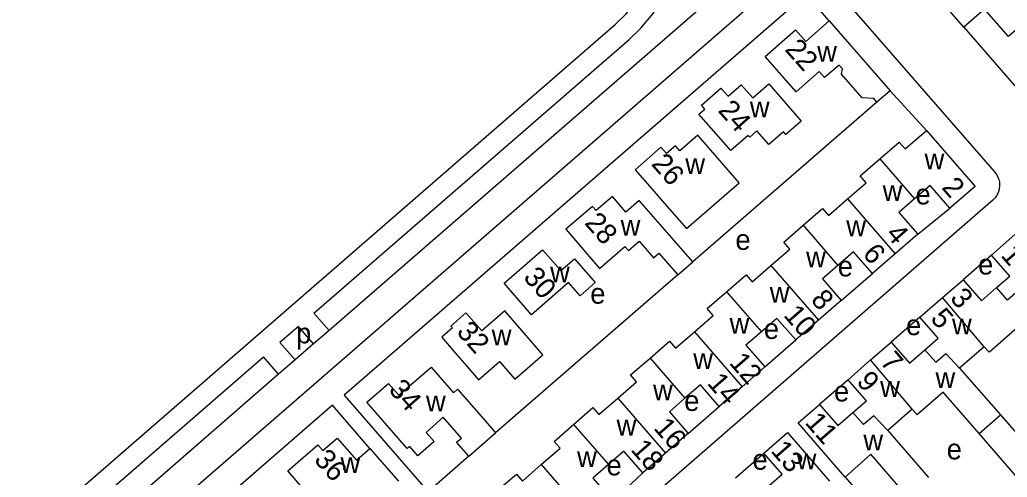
# Model space of a CAD drawing. Extents: x 155854 to 157362, y 383621 to 384685.
# Drawn here: x 155992.5 to 156185.4, y 384135.3 to 384224.7 of the extents above; entities that cross this region are included whole.
import ezdxf

# ---------------------------------------------------------------- set-up
doc = ezdxf.new("R2010")
doc.units = 0
for name, color, linetype in [('BLT_Basislijn', 7, 'Continuous'), ('BLT_Bebouwing', 7, 'Continuous'), ('BLT_Centroide', 7, 'Continuous'), ('BLT_Huisnummer', 7, 'Continuous'), ('BLT_Huisnummer_ tussenligend', 7, 'Continuous'), ('BLT_Onderverdeling_panden', 7, 'Continuous')]:
    doc.layers.add(name, color=color, linetype=linetype)

msp = doc.modelspace()

# ---------------------------------------------------------------- linework, layer by layer
at = {"layer": 'BLT_Basislijn'}
for p, q in [((156176.89, 384223.23), (156162.2, 384240.16)), ((156139.33, 384239), (156052.94, 384163.95)), ((156026.31, 384132.88), (156143.26, 384234.47)), ((156148.96, 384234.01), (156182.91, 384194.98)), ((156042.02, 384165.73), (156108.92, 384223.85)), ((156169.63, 384203.05), (156162.51, 384210.8)), ((156159.95, 384208.58), (156123.96, 384177.36)), ((156182.59, 384189.41), (156111.16, 384127.33)), ((156167.93, 384182.79), (156174.2, 384187.84)), ((156182.31, 384178.69), (156176.77, 384173.87)), ((156121.06, 384174.84), (156085.47, 384143.92)), ((156152.99, 384169.8), (156159.06, 384175.08)), ((156052.94, 384163.95), (156049.99, 384167.35)), ((156168.33, 384166.54), (156162.73, 384161.67)), ((155892.15, 384035.54), (156042.02, 384165.73)), ((156046.95, 384164.71), (156043.35, 384161.59)), ((156049.9, 384161.31), (156046.95, 384164.71)), ((156052.94, 384163.95), (156049.9, 384161.31)), ((156046.3, 384158.19), (156043.35, 384161.59)), ((156049.9, 384161.31), (156046.3, 384158.19)), ((156138.04, 384156.82), (156144.11, 384162.09)), ((156043.1, 384155.4), (156040.15, 384158.81)), ((156046.3, 384158.19), (156043.1, 384155.4)), ((156043.1, 384155.4), (155952.77, 384076.94)), ((156154.3, 384154.32), (156148.71, 384149.46)), ((156060.94, 384140.9), (156053.63, 384149.33)), ((156123.09, 384143.83), (156129.16, 384149.1)), ((156080.23, 384139.36), (156072.3, 384132.42)), ((156132.32, 384135.17), (156137.86, 384139.98)), ((156108.36, 384130.6), (156114.21, 384136.12)), ((156153.72, 384135.29), (156168.72, 384118.08))]:
    msp.add_line(p, q, dxfattribs=at)
for points in [[(156108.92, 384223.85), (156110.92, 384225.77), (156112.94, 384228.19), (156114.66, 384231.15), (156116.16, 384234.58)], [(156111.55, 384220.83), (156113.84, 384223.04), (156116.23, 384225.88), (156118.23, 384229.34), (156119.94, 384233.27)], [(156150.65, 384224.45), (156146.11, 384229.67), (156055.9, 384151.3), (156072.3, 384132.42)], [(156049.99, 384167.35), (156111.55, 384220.83)], [(156182.91, 384194.98), (156183.37, 384194.36), (156183.58, 384193.92), (156183.74, 384193.43), (156183.87, 384192.91), (156183.89, 384192.26), (156183.82, 384191.55), (156183.61, 384190.88), (156183.3, 384190.28), (156183.06, 384189.86), (156182.59, 384189.41)], [(155949.82, 384080.34), (156040.15, 384158.81)], [(156053.63, 384149.33), (155963.42, 384070.96), (155979.82, 384052.08)]]:
    msp.add_lwpolyline(points, dxfattribs=at)
at = {"layer": 'BLT_Bebouwing'}
for p, q in [((156146.04, 384220.44), (156150.65, 384224.45)), ((156138.14, 384217.52), (156144.07, 384222.69)), ((156144.07, 384222.69), (156146.04, 384220.44)), ((156125.68, 384207.99), (156129.49, 384211.31)), ((156129.49, 384211.31), (156130.87, 384209.72)), ((156130.87, 384209.72), (156133.45, 384211.98)), ((156133.45, 384211.98), (156135.68, 384209.42)), ((156135.68, 384209.42), (156138.81, 384212.14)), ((156138.81, 384212.14), (156145.18, 384204.88)), ((156125.18, 384206.22), (156126.35, 384207.23)), ((156126.35, 384207.23), (156125.68, 384207.99)), ((156131.39, 384199.1), (156125.18, 384206.22)), ((156145.18, 384204.88), (156142.15, 384202.23)), ((156136.51, 384202.98), (156135.1, 384201.75)), ((156138.86, 384200.3), (156136.51, 384202.98)), ((156141.68, 384202.77), (156138.86, 384200.3)), ((156142.15, 384202.23), (156141.68, 384202.77)), ((156124.99, 384202.14), (156121.45, 384199.06)), ((156133.07, 384192.84), (156124.99, 384202.14)), ((156134.8, 384202.09), (156131.39, 384199.1)), ((156135.1, 384201.75), (156134.8, 384202.09)), ((156117.75, 384199.78), (156112.71, 384195.37)), ((156118.85, 384198.52), (156117.75, 384199.78)), ((156120.59, 384200.04), (156118.85, 384198.52)), ((156121.45, 384199.06), (156120.59, 384200.04)), ((156122.75, 384183.85), (156133.07, 384192.84)), ((156108.28, 384190.11), (156105.1, 384187.38)), ((156110.88, 384187.07), (156108.28, 384190.11)), ((156113.54, 384189.35), (156110.88, 384187.07)), ((156123.96, 384177.36), (156113.54, 384189.35)), ((156104.4, 384188.19), (156099.2, 384183.73)), ((156105.1, 384187.38), (156104.4, 384188.19)), ((156099.2, 384183.73), (156105.75, 384176.08)), ((156167.93, 384182.79), (156163.5, 384178.93)), ((156087.12, 384173.17), (156094.65, 384179.74)), ((156094.65, 384179.74), (156098.2, 384175.66)), ((156105.75, 384176.08), (156110.73, 384180.35)), ((156110.73, 384180.35), (156111.4, 384179.57)), ((156111.4, 384179.57), (156113.49, 384181.39)), ((156113.49, 384181.39), (156116.31, 384178.15)), ((156098.2, 384175.66), (156100.86, 384177.98)), ((156100.86, 384177.98), (156104.92, 384173.32)), ((156163.5, 384178.93), (156159.06, 384175.08)), ((156172.76, 384170.39), (156176.77, 384173.87)), ((156092.5, 384167), (156087.12, 384173.17)), ((156099.74, 384173.31), (156092.5, 384167)), ((156101.97, 384170.75), (156099.74, 384173.31)), ((156104.92, 384173.32), (156101.97, 384170.75)), ((156168.33, 384166.54), (156172.76, 384170.39)), ((156152.99, 384169.8), (156148.55, 384165.95)), ((156079.68, 384167.4), (156076.7, 384164.82)), ((156082.76, 384163.86), (156079.68, 384167.4)), ((156087.26, 384167.77), (156082.76, 384163.86)), ((156094.67, 384159.2), (156087.26, 384167.77)), ((156077.03, 384164.45), (156074.95, 384162.64)), ((156076.7, 384164.82), (156077.03, 384164.45)), ((156148.55, 384165.95), (156144.11, 384162.09)), ((156158.72, 384158.18), (156162.73, 384161.67)), ((156089.2, 384154.45), (156094.67, 384159.2)), ((156070.04, 384154.33), (156072.88, 384156.79)), ((156072.88, 384156.79), (156077.25, 384151.77)), ((156082.15, 384154.31), (156086.24, 384157.86)), ((156086.24, 384157.86), (156089.2, 384154.45)), ((156138.04, 384156.82), (156133.6, 384152.96)), ((156154.3, 384154.32), (156158.72, 384158.18)), ((156060.35, 384149.93), (156064.57, 384153.6)), ((156064.57, 384153.6), (156066.56, 384151.3)), ((156066.56, 384151.3), (156070.04, 384154.33)), ((156133.6, 384152.96), (156129.16, 384149.1)), ((156077.25, 384151.77), (156078.04, 384152.46)), ((156078.04, 384152.46), (156083.1, 384146.65)), ((156068.23, 384140.86), (156060.35, 384149.93)), ((156144.56, 384145.86), (156148.71, 384149.46)), ((156075.26, 384146.97), (156071.89, 384144.03)), ((156083.1, 384146.65), (156085.47, 384143.92)), ((156153.72, 384135.29), (156144.56, 384145.86)), ((156071.89, 384144.03), (156073.46, 384142.22)), ((156080.23, 384139.36), (156085.47, 384143.92)), ((156044.89, 384136.49), (156050.76, 384141.61)), ((156050.76, 384141.61), (156051.76, 384140.47)), ((156051.76, 384140.47), (156054.55, 384142.9)), ((156054.55, 384142.9), (156058.3, 384138.6)), ((156068.71, 384141.28), (156068.23, 384140.86)), ((156070.29, 384139.46), (156068.71, 384141.28)), ((156073.46, 384142.22), (156070.29, 384139.46)), ((156058.3, 384138.6), (156060.94, 384140.9)), ((156118.64, 384139.96), (156114.21, 384136.12)), ((156050.28, 384130.32), (156044.89, 384136.49))]:
    msp.add_line(p, q, dxfattribs=at)
for points in [[(156189.28, 384224.58), (156185.65, 384221.42), (156180.99, 384226.79), (156176.89, 384223.23)], [(156150.65, 384224.45), (156162.51, 384210.8)], [(156176.89, 384223.23), (156193.22, 384204.44)], [(156152.55, 384215.82), (156149.72, 384213.37), (156148.69, 384214.55), (156144.16, 384210.61), (156138.14, 384217.52)], [(156159.95, 384208.58), (156159.32, 384209.31), (156157.05, 384209.45), (156153.05, 384214.06), (156153.2, 384215.07), (156152.55, 384215.82)], [(156162.51, 384210.8), (156159.95, 384208.58)], [(156160.49, 384197.49), (156164.28, 384200.79), (156165.46, 384199.43), (156169.63, 384203.05)], [(156169.63, 384203.05), (156179.13, 384192.12), (156174.2, 384187.84)], [(156154.19, 384189.65), (156157.87, 384192.84), (156156.69, 384194.2), (156160.49, 384197.49)], [(156112.71, 384195.37), (156116.02, 384191.57), (156118, 384189.3), (156122.75, 384183.85)], [(156174.2, 384187.84), (156170.32, 384192.3), (156167.29, 384189.66)], [(156145.53, 384184.51), (156149.33, 384187.81), (156150.51, 384186.45), (156154.19, 384189.65)], [(156167.29, 384189.66), (156164.25, 384187.02), (156167.93, 384182.79)], [(156139.24, 384176.66), (156142.92, 384179.86), (156141.74, 384181.22), (156145.53, 384184.51)], [(156182.31, 384178.69), (156186.9, 384182.7), (156195.11, 384173.27)], [(156116.31, 384178.15), (156117.38, 384179.08), (156121.06, 384174.84)], [(156159.06, 384175.08), (156155.38, 384179.31), (156152.34, 384176.67)], [(156183.33, 384172.36), (156185.89, 384174.59), (156182.31, 384178.69)], [(156121.06, 384174.84), (156123.96, 384177.36)], [(156130.58, 384171.53), (156134.38, 384174.83), (156135.56, 384173.47), (156139.24, 384176.66)], [(156152.34, 384176.67), (156149.31, 384174.04), (156152.99, 384169.8)], [(156176.77, 384173.87), (156180.34, 384169.76), (156183.33, 384172.36)], [(156124.29, 384163.68), (156127.97, 384166.88), (156126.79, 384168.23), (156130.58, 384171.53)], [(156144.11, 384162.09), (156140.43, 384166.32), (156137.4, 384163.69)], [(156169.33, 384160.18), (156171.91, 384162.42), (156168.33, 384166.54)], [(156074.95, 384162.64), (156077.54, 384159.67), (156079.81, 384157.03), (156082.15, 384154.31)], [(156115.64, 384158.55), (156119.43, 384161.85), (156120.61, 384160.49), (156124.29, 384163.68)], [(156137.4, 384163.69), (156134.36, 384161.05), (156138.04, 384156.82)], [(156193.94, 384156.01), (156186.91, 384164.09), (156181.97, 384159.8)], [(156162.73, 384161.67), (156166.31, 384157.56), (156169.33, 384160.18)], [(156180.89, 384160.77), (156176.09, 384156.6)], [(156181.97, 384159.8), (156181.84, 384159.68), (156180.89, 384160.77)], [(156109.34, 384150.71), (156113.02, 384153.89), (156111.84, 384155.25), (156115.64, 384158.55)], [(156176.09, 384156.6), (156184.07, 384147.43)], [(156129.16, 384149.1), (156125.48, 384153.34), (156122.45, 384150.7)], [(156155.27, 384147.94), (156157.88, 384150.21), (156154.3, 384154.32)], [(156100.68, 384145.57), (156104.48, 384148.87), (156105.66, 384147.51), (156109.34, 384150.71)], [(156122.45, 384150.7), (156119.41, 384148.07), (156123.09, 384143.83)], [(156179.9, 384143.79), (156172.88, 384151.88), (156167.93, 384147.59)], [(156148.71, 384149.46), (156152.28, 384145.34), (156155.27, 384147.94)], [(156080.23, 384139.36), (156077.86, 384142.09), (156078.8, 384142.9), (156075.26, 384146.97)], [(156166.85, 384148.56), (156162.05, 384144.39)], [(156167.93, 384147.59), (156167.8, 384147.47), (156166.85, 384148.56)], [(156184.07, 384147.43), (156191.1, 384139.35), (156196.03, 384143.64)], [(156094.39, 384137.72), (156098.06, 384140.91), (156096.89, 384142.27), (156100.68, 384145.57)], [(156123.09, 384143.83), (156122.84, 384143.61), (156118.64, 384139.96)], [(156137.86, 384139.98), (156142.46, 384143.98), (156150.68, 384134.48)], [(156162.05, 384144.39), (156170.02, 384135.21)], [(156187.88, 384134.62), (156179.9, 384143.79)], [(156060.94, 384140.9), (156066.5, 384134.49)], [(156114.21, 384136.12), (156110.54, 384140.36), (156107.5, 384137.72)], [(156138.9, 384133.67), (156141.44, 384135.87), (156137.86, 384139.98)], [(156165.85, 384131.58), (156158.75, 384139.74), (156153.72, 384135.29)], [(156085.74, 384132.59), (156089.53, 384135.88), (156090.71, 384134.52), (156094.39, 384137.72)], [(156107.5, 384137.72), (156104.46, 384135.08), (156108.14, 384130.85), (156108.36, 384130.6)]]:
    msp.add_lwpolyline(points, dxfattribs=at)
at = {"layer": 'BLT_Onderverdeling_panden'}
for p, q in [((156160.49, 384197.49), (156167.29, 384189.66)), ((156154.19, 384189.65), (156163.5, 384178.93)), ((156145.53, 384184.51), (156152.34, 384176.67)), ((156139.24, 384176.66), (156148.55, 384165.95)), ((156130.58, 384171.53), (156137.4, 384163.69)), ((156180.89, 384160.77), (156172.76, 384170.39)), ((156124.29, 384163.68), (156133.6, 384152.96)), ((156115.64, 384158.55), (156122.45, 384150.7)), ((156166.85, 384148.56), (156158.72, 384158.18)), ((156109.34, 384150.71), (156118.64, 384139.96)), ((156179.9, 384143.79), (156184.07, 384147.43)), ((156100.68, 384145.57), (156107.5, 384137.72)), ((156094.39, 384137.72), (156103.92, 384126.74))]:
    msp.add_line(p, q, dxfattribs=at)
for points in [[(156190.05, 384168.86), (156187.58, 384171.73), (156185.47, 384169.9), (156183.33, 384172.36)], [(156169.33, 384160.18), (156171.44, 384157.75), (156173.41, 384159.46), (156176.09, 384156.6)], [(156162.05, 384144.39), (156159.33, 384147.25), (156157.34, 384145.54), (156155.27, 384147.94)]]:
    msp.add_lwpolyline(points, dxfattribs=at)

# ---------------------------------------------------------------- texts
at = {"layer": 'BLT_Centroide'}
for s, p in [('w', (156148.28, 384216.5)), ('w', (156135.12, 384205.62)), ('w', (156122.52, 384194.53)), ('w', (156169.25, 384195.44)), ('w', (156161.06, 384189.28)), ('e', (156167.48, 384188.59)), ('w', (156109.89, 384182.47)), ('w', (156153.96, 384182.38)), ('e', (156132.31, 384179.7)), ('w', (156146.11, 384176.3)), ('e', (156179.7, 384174.88)), ('w', (156096.11, 384173.38)), ('e', (156152.3, 384174.51)), ('e', (156103.96, 384169.18)), ('w', (156139.01, 384169.38)), ('w', (156131.17, 384163.31)), ('e', (156165.63, 384163.03)), ('w', (156174.61, 384163.19)), ('p', (156046.49, 384161.42)), ('e', (156137.86, 384162.29)), ('w', (156084.71, 384161.03)), ('w', (156124.07, 384156.41)), ('w', (156171.39, 384152.72)), ('w', (156116.22, 384150.31)), ('e', (156151.56, 384150.07)), ('w', (156160.58, 384150.97)), ('w', (156071.87, 384148.12)), ('e', (156122.31, 384148.22)), ('w', (156109.11, 384143.41)), ('w', (156157.3, 384140.53)), ('e', (156173.58, 384138.75)), ('w', (156055.18, 384136.09)), ('w', (156101.38, 384137.23)), ('e', (156135.64, 384136.73)), ('w', (156144.27, 384136.8)), ('e', (156107.13, 384135.62))]:
    msp.add_text(s, height=4, dxfattribs=at).set_placement(p)
at = {"layer": 'BLT_Huisnummer'}
for s, rotation, p in [('22', 311.4651, (156141.81, 384218.8)), ('24', 311.4651, (156128.76, 384206.85)), ('26', 311.4651, (156115.72, 384196.41)), ('2', 310.9768, (156172.44, 384191.81)), ('28', 311.4651, (156102.68, 384184.88)), ('1', 310.9773, (156184, 384178.54)), ('30', 311.4651, (156090.72, 384174.23)), ('3', 310.9773, (156174.06, 384170.15)), ('8', 310.9768, (156146.87, 384169.83)), ('10', 310.9768, (156141.55, 384166.86)), ('32', 311.4651, (156077.68, 384163.57)), ('9', 310.9773, (156155.8, 384153.86)), ('34', 311.4651, (156064.41, 384152.27)), ('11', 310.9773, (156145.74, 384145.86)), ('16', 310.9768, (156116.18, 384144.8)), ('18', 310.9768, (156111.71, 384140.59)), ('13', 310.9773, (156139.07, 384140.34)), ('36', 311.4651, (156049.84, 384138.57))]:
    msp.add_text(s, height=4, rotation=rotation, dxfattribs=at).set_placement(p)
at = {"layer": 'BLT_Huisnummer_ tussenligend'}
for s, rotation, p in [('4', 310.9768, (156161.5, 384182.68)), ('6', 310.9768, (156156.97, 384178.81)), ('5', 310.9773, (156170.24, 384166.18)), ('12', 310.9768, (156130.94, 384157.55)), ('7', 310.9773, (156160.41, 384157.7)), ('14', 310.9768, (156126.63, 384153.57))]:
    msp.add_text(s, height=4, rotation=rotation, dxfattribs=at).set_placement(p)

doc.saveas('drawing.dxf')
